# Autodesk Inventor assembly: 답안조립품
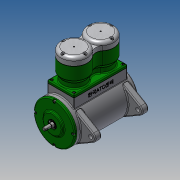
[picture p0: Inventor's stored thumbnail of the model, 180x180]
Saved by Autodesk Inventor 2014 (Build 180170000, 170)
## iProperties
Created: 2019-08
Part Number: 답안조립품
Document SubType Name: Assembly
Designer: kb542
Author: kb542
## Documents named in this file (18)
- C:\Users\kb542\Desktop\390804V1016\답안조립품.iam
- C:\Users\kb542\Desktop\390804V1016\본체.ipt
- C:\Users\kb542\Desktop\390804V1016\크랭크축.ipt
- C:\Users\kb542\Desktop\390804V1016\베어링 12 x 28 x 8.ipt
- C:\Users\kb542\Desktop\390804V1016\앞커버.ipt
- C:\Users\kb542\Desktop\390804V1016\오일 실 12 25 7.ipt
- C:\Users\kb542\Desktop\390804V1016\볼트 M4 x 8.ipt
- C:\Users\kb542\Desktop\390804V1016\실린더 개스킷.ipt
- C:\Users\kb542\Desktop\390804V1016\실린더.ipt
- C:\Users\kb542\Desktop\390804V1016\실린더헤드 개스킷.ipt
- C:\Users\kb542\Desktop\390804V1016\실린더헤드.ipt
- C:\Users\kb542\Desktop\390804V1016\볼트 M5 x 20.ipt
- C:\Users\kb542\Desktop\390804V1016\커넥팅로드.ipt
- C:\Users\kb542\Desktop\390804V1016\커넥팅로드 엔드.ipt
- C:\Users\kb542\Desktop\390804V1016\피스톤.ipt
- C:\Users\kb542\Desktop\390804V1016\육각 머리 볼트 M4 x 16.ipt
- C:\Users\kb542\Desktop\390804V1016\너트 M4.ipt
- C:\Users\kb542\Desktop\390804V1016\피스톤핀.ipt
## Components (4 placed, 2 different names)
1. 피스톤:1 — 플러쉬:1
2. 피스톤핀:1
3. 피스톤:2 — 플러쉬:2
4. 피스톤핀:2
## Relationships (2: Flush 2)
- 플러쉬:1 [Flush]: 피스톤:1
- 플러쉬:2 [Flush]: 피스톤:2
